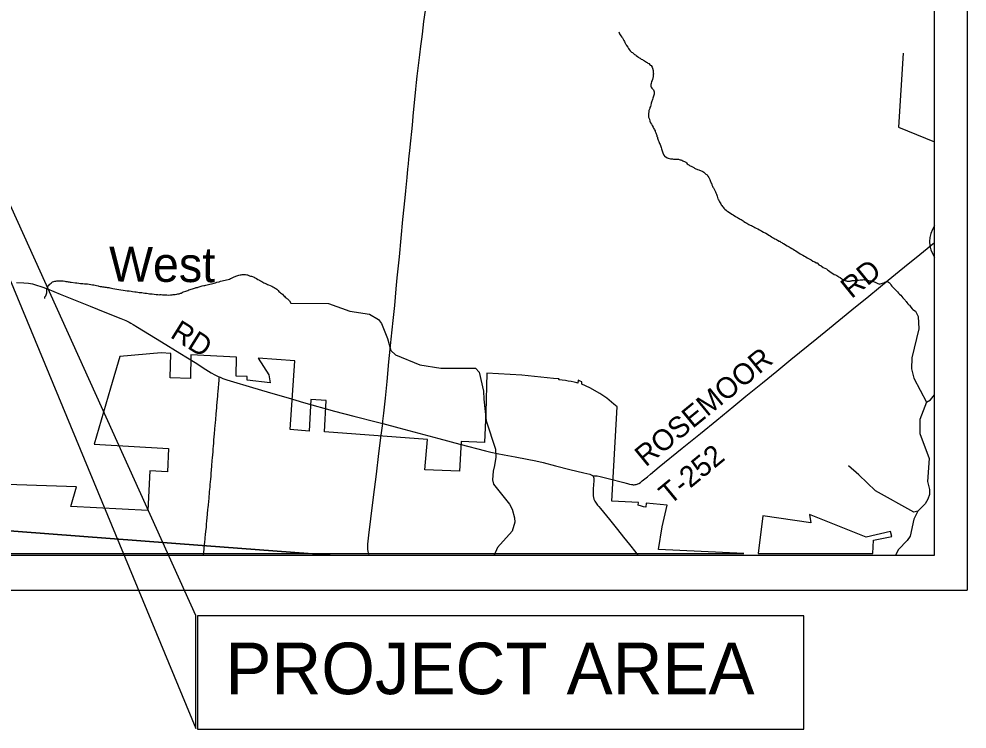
# Model space of a CAD drawing. Extents: x -5.4 to 49.9, y 13.2 to 48.4.
# Drawn here: x 30.593 to 33.165, y 40.172 to 42.099 of the extents above; entities that cross this region are included whole.
import ezdxf

# ---------------------------------------------------------------- set-up
doc = ezdxf.new("R2010")
doc.units = 0
for name, color, linetype in [('GM_X_Corporation', 7, 'Continuous'), ('GM_X_County_Road', 7, 'Continuous'), ('GM_X_County_Road_Text', 7, 'Continuous'), ('GM_X_Minor_River', 7, 'Continuous'), ('GM_X_Minor_River_Text', 7, 'Continuous'), ('GM_X_Township', 7, 'Continuous'), ('GM_X_Township_Road', 7, 'Continuous'), ('GM_X_Township_Road_Text', 7, 'Continuous'), ('GM_X_Unincorporated', 7, 'Continuous'), ('SH_Data', 7, 'Continuous'), ('SH_Text', 7, 'Continuous')]:
    doc.layers.add(name, color=color, linetype=linetype)

msp = doc.modelspace()

# ---------------------------------------------------------------- linework, layer by layer
at = {"layer": 'GM_X_Corporation'}
for p, q in [((30.2983, 40.6483), (32.5599, 40.6483)), ((32.5989, 40.6483), (32.9095, 40.6483))]:
    msp.add_line(p, q, dxfattribs=at)
for points in [[(32.5599, 40.6483), (32.3284, 40.6593), (32.3384, 40.7205), (32.352, 40.7792), (32.2946, 40.7848), (32.2935, 40.774), (32.2876, 40.7746), (32.2819, 40.7767), (32.2731, 40.7795), (32.2737, 40.7863), (32.2012, 40.7907), (32.2161, 41.0465), (32.2066, 41.0538), (32.1877, 41.0698), (32.1687, 41.083), (32.1417, 41.0976), (32.1201, 41.1078), (32.1204, 41.1139), (32.1158, 41.1162), (32.1099, 41.1187), (32.1095, 41.1109), (32.1062, 41.1117), (32.0993, 41.1134), (32.0911, 41.1151), (32.0832, 41.1165), (32.0755, 41.1177), (32.067, 41.1188), (32.058, 41.1197), (32.0582, 41.1226), (32.0437, 41.1235), (31.9571, 41.132), (31.8626, 41.1378), (31.8598, 41.0314), (31.8558, 40.9495), (31.793, 40.9527), (31.7884, 40.8713), (31.6943, 40.8754), (31.701, 40.9573), (31.4217, 40.9782), (31.4263, 41.0635), (31.3852, 41.0659), (31.3806, 40.9806), (31.3287, 40.9844), (31.341, 41.1714), (31.242, 41.1783), (31.271, 41.1337), (31.2748, 41.1119), (31.2125, 41.1187), (31.2125, 41.1286), (31.1825, 41.1299), (31.1833, 41.1814), (31.0595, 41.188), (31.058, 41.1229), (31.0031, 41.1251), (31.0054, 41.1909), (30.9785, 41.1928), (30.867, 41.183), (30.8414, 41.0973), (30.7971, 40.9452), (30.9983, 40.9337), (30.9961, 40.8703), (30.9477, 40.873), (30.9423, 40.765), (30.7337, 40.7761), (30.7487, 40.8288), (30.2884, 40.8443)], [(32.9095, 40.6483), (32.9114, 40.6846), (32.9609, 40.6942), (32.9579, 40.7081), (32.892, 40.6921), (32.7375, 40.7541), (32.7416, 40.7318), (32.611, 40.75), (32.5989, 40.6483)]]:
    msp.add_lwpolyline(points, dxfattribs=at)
at = {"layer": 'GM_X_County_Road'}
for points in [[(31.5798, 41.0007), (31.5805, 41.0071), (31.5826, 41.0288), (31.587, 41.0696), (31.5916, 41.1153), (31.5968, 41.1685), (31.6003, 41.2031), (31.603, 41.2297), (31.6082, 41.281), (31.6123, 41.3218), (31.6167, 41.3663), (31.6194, 41.3966), (31.6254, 41.454), (31.6349, 41.5549), (31.6407, 41.6136), (31.6425, 41.6328), (31.646, 41.6687), (31.6481, 41.6916), (31.6495, 41.7064), (31.6508, 41.7188), (31.6541, 41.7503), (31.6552, 41.7608), (31.6594, 41.8022), (31.6615, 41.822), (31.6628, 41.8356), (31.6701, 41.9086), (31.6719, 41.9265), (31.6737, 41.9438), (31.6763, 41.966), (31.6794, 41.9951), (31.6803, 42.0019), (31.6834, 42.0259), (31.6858, 42.0444), (31.6875, 42.0579), (31.6918, 42.0924), (31.6955, 42.1226)], [(30.5864, 41.3841), (30.6063, 41.383), (30.6187, 41.3819), (30.6298, 41.38), (30.6407, 41.3771), (30.6525, 41.373), (30.6699, 41.3663), (30.7051, 41.3522), (30.7863, 41.3194), (30.8255, 41.3035), (30.8694, 41.2861), (30.8826, 41.2805), (30.8916, 41.2763), (30.8966, 41.2737), (30.9032, 41.2701), (30.9149, 41.2629), (30.9307, 41.2531), (30.9799, 41.2228), (31.0295, 41.192), (31.0706, 41.1663), (31.0995, 41.148), (31.1148, 41.1386), (31.124, 41.1334), (31.1313, 41.1297), (31.1364, 41.1274)], [(31.1364, 41.1274), (31.1385, 41.1265), (31.1459, 41.1235), (31.157, 41.1197), (31.1749, 41.1142), (31.2172, 41.102), (31.2756, 41.0845), (31.3232, 41.0704), (31.365, 41.0582), (31.4488, 41.035), (31.5017, 41.0211), (31.5654, 41.0044), (31.5798, 41.0007)], [(31.5401, 40.6551), (31.5397, 40.6569), (31.5392, 40.6604), (31.5391, 40.6665), (31.5395, 40.6733), (31.5424, 40.6979), (31.548, 40.7423), (31.5525, 40.7793), (31.5577, 40.8219), (31.5628, 40.8632), (31.5694, 40.9194), (31.5755, 40.9693), (31.5798, 41.0007)], [(31.5798, 41.0007), (31.6232, 40.9895), (31.7318, 40.9605), (31.7895, 40.9453), (31.8591, 40.9267), (31.873, 40.9233), (31.8906, 40.9196), (31.9095, 40.916), (31.9389, 40.9108), (31.9719, 40.9045), (31.995, 40.8996), (32.015, 40.895), (32.0487, 40.8864), (32.0879, 40.8765), (32.1253, 40.8672), (32.1416, 40.8632), (32.1452, 40.862), (32.147, 40.8612), (32.1487, 40.8601), (32.1501, 40.8587)], [(32.1501, 40.8587), (32.1501, 40.8586), (32.1509, 40.8575), (32.152, 40.855), (32.1524, 40.8524), (32.1525, 40.8499), (32.1524, 40.8454), (32.1512, 40.8237), (32.1507, 40.8138), (32.1507, 40.8095), (32.151, 40.8046), (32.1516, 40.8001), (32.1531, 40.7956), (32.1557, 40.7903), (32.1594, 40.7847), (32.163, 40.7797), (32.1662, 40.7758), (32.1704, 40.7705), (32.1952, 40.7402), (32.2166, 40.7135), (32.2335, 40.6929), (32.2493, 40.6729), (32.2667, 40.6509), (32.2725, 40.6437)], [(31.5435, 40.6437), (31.5422, 40.6471), (31.5411, 40.6504), (31.5403, 40.6538), (31.5401, 40.6551)]]:
    msp.add_lwpolyline(points, dxfattribs=at)
at = {"layer": 'GM_X_Minor_River'}
for points in [[(32.2207, 42.0642), (32.2221, 42.0589), (32.2259, 42.0539), (32.2289, 42.0504), (32.2307, 42.0485), (32.2311, 42.0466), (32.2322, 42.0443), (32.2341, 42.0409), (32.2356, 42.0382), (32.2367, 42.0355), (32.2378, 42.0336), (32.2389, 42.0317), (32.24, 42.0298), (32.2411, 42.0275), (32.2445, 42.0225), (32.2464, 42.0195), (32.2486, 42.0168), (32.2516, 42.013), (32.2535, 42.0114), (32.255, 42.0095), (32.2573, 42.0083), (32.2595, 42.0064), (32.2614, 42.0052), (32.2633, 42.0033), (32.2655, 42.0022), (32.2678, 42.0002), (32.2716, 41.9972), (32.2738, 41.9956), (32.2757, 41.9941), (32.278, 41.9929), (32.2814, 41.9906), (32.2844, 41.989), (32.2863, 41.9879), (32.2885, 41.9867), (32.2904, 41.9855), (32.2927, 41.984), (32.2953, 41.9824), (32.2972, 41.9813), (32.2995, 41.9797), (32.3017, 41.9786), (32.3055, 41.9744), (32.3081, 41.9728), (32.3107, 41.9682), (32.3122, 41.9663), (32.3133, 41.9591), (32.314, 41.9534), (32.3143, 41.9507), (32.3135, 41.9473), (32.3135, 41.9442), (32.3135, 41.9416), (32.3127, 41.9393), (32.3119, 41.9351), (32.3107, 41.9321), (32.3095, 41.9295), (32.308, 41.9242), (32.3072, 41.9211), (32.3072, 41.9189), (32.3075, 41.917), (32.3086, 41.9143), (32.3105, 41.9116), (32.3127, 41.9089), (32.3146, 41.907), (32.3157, 41.9043), (32.3161, 41.902), (32.3164, 41.8994), (32.3164, 41.8975), (32.316, 41.8952), (32.3132, 41.8842), (32.3121, 41.8812), (32.3109, 41.8785), (32.3101, 41.8759), (32.3093, 41.8732), (32.3085, 41.8706), (32.3074, 41.8657), (32.3062, 41.8619), (32.305, 41.8592), (32.3042, 41.8566), (32.3038, 41.8543), (32.303, 41.8524), (32.3023, 41.8505), (32.3019, 41.8482), (32.3015, 41.8456), (32.3011, 41.8437), (32.301, 41.8414), (32.301, 41.8391), (32.301, 41.8365), (32.3013, 41.8327), (32.3024, 41.8289), (32.3035, 41.827), (32.3046, 41.8224), (32.3068, 41.8178), (32.3087, 41.8136), (32.3109, 41.8098), (32.3135, 41.8056), (32.315, 41.8029), (32.3165, 41.8006), (32.3176, 41.7983), (32.3188, 41.7956), (32.3195, 41.7937), (32.321, 41.7899), (32.3232, 41.7834)], [(32.9918, 42.0065), (32.9795, 41.8053), (33.0771, 41.7658)], [(32.3232, 41.7834), (32.3239, 41.7804), (32.325, 41.7781), (32.3258, 41.7758), (32.3265, 41.7735), (32.3276, 41.7704), (32.3291, 41.7666), (32.3302, 41.764), (32.3313, 41.7609), (32.3324, 41.7582), (32.3335, 41.7556), (32.3342, 41.7533), (32.335, 41.7506), (32.3361, 41.7472), (32.3372, 41.7445), (32.3379, 41.7415), (32.339, 41.7384), (32.3401, 41.7361), (32.3427, 41.7296), (32.3457, 41.7262), (32.3476, 41.725), (32.3518, 41.7223), (32.3548, 41.7211), (32.3604, 41.7195), (32.3639, 41.7195), (32.3658, 41.7195), (32.3684, 41.7191), (32.3768, 41.719), (32.3802, 41.7186), (32.3821, 41.7185), (32.384, 41.7181), (32.3866, 41.7173), (32.3889, 41.7169), (32.3911, 41.7158), (32.3938, 41.7146), (32.3961, 41.7138), (32.3991, 41.7123), (32.4021, 41.7107), (32.404, 41.7084), (32.4062, 41.7061), (32.4089, 41.7042), (32.4107, 41.703), (32.4126, 41.7015), (32.4145, 41.7003), (32.4164, 41.6995), (32.4187, 41.6987), (32.4221, 41.6968), (32.4239, 41.696), (32.4258, 41.6945), (32.4296, 41.6929), (32.4322, 41.6918), (32.4341, 41.691), (32.4372, 41.6894), (32.439, 41.689), (32.4421, 41.6878), (32.444, 41.6867), (32.4462, 41.6859), (32.4481, 41.6851), (32.4511, 41.6839), (32.4534, 41.6813), (32.4564, 41.6782), (32.4598, 41.6766), (32.462, 41.6728), (32.4643, 41.6686), (32.4665, 41.6655), (32.4676, 41.6632), (32.4683, 41.661), (32.4691, 41.6583), (32.4702, 41.656), (32.4713, 41.6537), (32.4724, 41.6514), (32.4732, 41.6491), (32.4746, 41.6457), (32.4757, 41.643), (32.4772, 41.6411), (32.4791, 41.6373), (32.481, 41.6335), (32.4824, 41.6304), (32.4839, 41.6277), (32.485, 41.6254), (32.4858, 41.6235), (32.4865, 41.6209), (32.4869, 41.6182), (32.4883, 41.6144), (32.4895, 41.6113), (32.4906, 41.6094), (32.4921, 41.6064), (32.4935, 41.6025), (32.4954, 41.5999), (32.4969, 41.5972), (32.4984, 41.5945), (32.5003, 41.5926), (32.5018, 41.5907), (32.5032, 41.5884), (32.5055, 41.5857), (32.5081, 41.5834), (32.5115, 41.5803), (32.5138, 41.5784), (32.516, 41.5768), (32.5232, 41.5722), (32.527, 41.5695)], [(32.527, 41.5695), (32.5311, 41.5672), (32.5341, 41.5652), (32.536, 41.5644), (32.5386, 41.5625), (32.5405, 41.5614), (32.5428, 41.5602), (32.5451, 41.559), (32.5473, 41.5575), (32.55, 41.5559), (32.5526, 41.5548), (32.5549, 41.5532), (32.5575, 41.5517), (32.5601, 41.5497), (32.5639, 41.547), (32.5677, 41.5447), (32.5733, 41.5416), (32.5767, 41.54), (32.5801, 41.5385), (32.5831, 41.5369), (32.5865, 41.5354), (32.5899, 41.5334), (32.5933, 41.5315), (32.5975, 41.5292), (32.602, 41.5268), (32.6058, 41.5249), (32.6088, 41.523), (32.6129, 41.5203), (32.619, 41.5175), (32.6235, 41.5148), (32.6277, 41.5125), (32.6311, 41.5106), (32.6344, 41.5082), (32.6375, 41.5063), (32.6409, 41.5044), (32.6439, 41.5028), (32.6461, 41.5013), (32.6484, 41.5005), (32.6514, 41.4989), (32.6552, 41.4966), (32.6571, 41.4958), (32.6601, 41.4935), (32.6624, 41.4923), (32.665, 41.4908), (32.6673, 41.4896), (32.6774, 41.4831), (32.6823, 41.4807), (32.6857, 41.4788), (32.6899, 41.4765), (32.6933, 41.4741), (32.697, 41.4718), (32.7008, 41.4695), (32.7046, 41.4668), (32.7087, 41.4641), (32.7129, 41.4621), (32.7163, 41.4598), (32.7197, 41.4579), (32.7242, 41.4555), (32.7276, 41.4536), (32.7317, 41.4509), (32.7366, 41.4478), (32.7423, 41.4451), (32.7472, 41.442), (32.7521, 41.4397), (32.7563, 41.4377), (32.7589, 41.4369), (32.7634, 41.4323), (32.7694, 41.4288), (32.7751, 41.425), (32.7796, 41.4226), (32.7838, 41.4207), (32.7864, 41.4187), (32.7898, 41.4164), (32.7928, 41.4137), (32.797, 41.411), (32.8015, 41.4083), (32.8052, 41.406), (32.8086, 41.4044), (32.8117, 41.4029), (32.8143, 41.401), (32.8169, 41.3994), (32.8196, 41.3982), (32.8215, 41.3971), (32.826, 41.3936), (32.8286, 41.3924), (32.8309, 41.3909), (32.8362, 41.3889), (32.8381, 41.3882), (32.84, 41.3877), (32.8426, 41.3877), (32.8449, 41.3877), (32.8479, 41.388), (32.8498, 41.3884), (32.8521, 41.3888), (32.854, 41.3891), (32.8563, 41.3895), (32.8582, 41.3894), (32.8605, 41.3898), (32.8631, 41.3901), (32.8673, 41.3905), (32.8707, 41.3904)], [(31.0209, 41.3524), (31.0239, 41.3528), (31.0274, 41.3535), (31.0308, 41.3546), (31.0331, 41.3549), (31.0354, 41.3564), (31.0384, 41.3583), (31.0418, 41.3594), (31.0456, 41.3605), (31.0483, 41.3616), (31.051, 41.3623), (31.054, 41.3638), (31.0578, 41.3645), (31.0605, 41.3657), (31.0635, 41.3668), (31.0662, 41.3675), (31.0689, 41.3686), (31.0715, 41.3693), (31.0738, 41.3701), (31.0772, 41.3708), (31.0795, 41.3715), (31.0818, 41.3723), (31.0849, 41.3734), (31.0902, 41.3748), (31.0944, 41.3755), (31.097, 41.3759), (31.0997, 41.377), (31.1035, 41.3777), (31.1069, 41.3784), (31.1107, 41.3795), (31.1149, 41.3806), (31.1259, 41.3832), (31.1301, 41.3846), (31.1358, 41.3857), (31.14, 41.3872), (31.1442, 41.3883), (31.148, 41.3894), (31.1522, 41.3905), (31.1564, 41.3916), (31.1606, 41.3923), (31.164, 41.3934), (31.167, 41.3945), (31.1697, 41.3956), (31.1728, 41.3974), (31.177, 41.3989), (31.1796, 41.4), (31.1815, 41.4008), (31.1838, 41.4019), (31.1869, 41.403), (31.1899, 41.4037), (31.1933, 41.4048), (31.196, 41.4052), (31.1987, 41.4055), (31.2009, 41.4059), (31.2032, 41.4058), (31.2051, 41.4058), (31.2078, 41.4054), (31.2108, 41.405), (31.2127, 41.4046), (31.2165, 41.403), (31.2187, 41.4022), (31.221, 41.4015), (31.224, 41.4007), (31.227, 41.3999), (31.2312, 41.3987), (31.2342, 41.3968), (31.2376, 41.3948), (31.2414, 41.3925), (31.2452, 41.3902), (31.2486, 41.3882), (31.2519, 41.3863), (31.255, 41.3847), (31.2572, 41.3832), (31.2599, 41.3824), (31.2621, 41.3812), (31.2644, 41.3801), (31.2674, 41.3789), (31.2704, 41.3777), (31.2788, 41.3738), (31.2818, 41.3719), (31.2852, 41.37), (31.2878, 41.3684), (31.2901, 41.3672), (31.2923, 41.3657), (31.2965, 41.3619), (31.2983, 41.3599), (31.3006, 41.3576), (31.3028, 41.3557), (31.3051, 41.3545), (31.3077, 41.3522), (31.3107, 41.3488), (31.313, 41.3465), (31.3152, 41.3442), (31.3179, 41.3422), (31.3198, 41.3407), (31.3216, 41.3395), (31.3239, 41.3372), (31.3265, 41.3345), (31.3303, 41.3282)], [(32.8707, 41.3904), (32.8753, 41.3911), (32.8795, 41.3911), (32.8825, 41.3914), (32.8848, 41.3918), (32.8874, 41.3914), (32.8893, 41.3914), (32.892, 41.391), (32.8946, 41.3906), (32.8992, 41.3897), (32.9022, 41.3889), (32.9045, 41.3889), (32.9064, 41.3881), (32.9098, 41.3873), (32.9117, 41.3866), (32.9135, 41.3858), (32.9162, 41.3846), (32.92, 41.383), (32.923, 41.3815), (32.9256, 41.3799), (32.9279, 41.3792), (32.9298, 41.3803), (32.9397, 41.3832), (32.9424, 41.3847), (32.9447, 41.3858), (32.9473, 41.3865), (32.9496, 41.3865), (32.9519, 41.385), (32.9549, 41.3834), (32.9564, 41.3815), (32.9582, 41.3777), (32.9612, 41.3742), (32.9639, 41.3712), (32.9669, 41.3681), (32.9687, 41.3665), (32.9706, 41.365), (32.974, 41.3612), (32.977, 41.3585), (32.9792, 41.3554), (32.9819, 41.3523), (32.9853, 41.3493), (32.9886, 41.3458), (32.9909, 41.3427), (32.9935, 41.3397), (32.9958, 41.3377), (32.9973, 41.3358), (32.9987, 41.3339), (33.0002, 41.332), (33.0021, 41.3293), (33.0044, 41.3262), (33.007, 41.3236), (33.0089, 41.322), (33.0126, 41.3174), (33.016, 41.3128), (33.0186, 41.3109), (33.0255, 41.3059)], [(30.6633, 41.3405), (30.6634, 41.3447), (30.6661, 41.3481), (30.6681, 41.3556), (30.6685, 41.3575), (30.6685, 41.3602), (30.6685, 41.3625), (30.6689, 41.3651), (30.6693, 41.3674), (30.6701, 41.3697), (30.6713, 41.3719), (30.6713, 41.3746), (30.674, 41.3761), (30.6755, 41.3784), (30.6778, 41.3802), (30.6805, 41.3825), (30.6824, 41.3836), (30.6839, 41.3855), (30.6874, 41.3866), (30.69, 41.3873), (30.6927, 41.3877), (30.6961, 41.3884), (30.6991, 41.3887), (30.7026, 41.3887), (30.7067, 41.3886), (30.7101, 41.3886), (30.7132, 41.3882), (30.7173, 41.3878), (30.7204, 41.387), (30.7234, 41.3866), (30.7264, 41.3861), (30.7291, 41.3854), (30.7317, 41.3849), (30.7348, 41.3845), (30.7461, 41.3833), (30.7503, 41.3828), (30.7556, 41.3824), (30.7598, 41.3816), (30.7658, 41.3811), (30.7708, 41.3807), (30.7746, 41.3803), (30.7787, 41.3799), (30.7837, 41.379), (30.7882, 41.3786), (30.7924, 41.3778), (30.7962, 41.3774), (30.7999, 41.3766), (30.8037, 41.3754), (30.8075, 41.375), (30.8098, 41.3742), (30.8136, 41.3734), (30.817, 41.373), (30.82, 41.3725), (30.823, 41.3718), (30.8257, 41.3717), (30.8291, 41.3713), (30.8325, 41.3705), (30.8367, 41.3701), (30.8397, 41.3697), (30.8439, 41.3689), (30.8473, 41.3677), (30.8526, 41.3669), (30.8583, 41.366), (30.8643, 41.3648), (30.8696, 41.364), (30.8757, 41.3632), (30.8814, 41.3624), (30.8867, 41.3615), (30.892, 41.3611), (30.8969, 41.3603), (30.9007, 41.3595), (30.9071, 41.3586), (30.9113, 41.3582), (30.9155, 41.3578), (30.9193, 41.357), (30.9227, 41.3566), (30.9261, 41.3565), (30.9295, 41.3557), (30.934, 41.3553), (30.939, 41.3549), (30.9435, 41.3541), (30.9473, 41.3536), (30.9515, 41.3528), (30.9541, 41.3528), (30.9651, 41.3512), (30.9693, 41.3511), (30.9731, 41.3507), (30.9761, 41.351), (30.9788, 41.351), (30.9825, 41.3506), (30.9856, 41.3502), (30.9879, 41.3501), (30.9909, 41.3501), (30.9943, 41.3501), (30.9989, 41.35), (31.0038, 41.3503), (31.0084, 41.3507), (31.0114, 41.351), (31.0141, 41.3514), (31.0163, 41.3517), (31.0209, 41.3524)], [(31.3303, 41.3282), (31.4329, 41.3269)], [(31.4329, 41.3269), (31.4909, 41.3063), (31.5437, 41.2984), (31.5683, 41.2833), (31.577, 41.273), (31.5929, 41.2321), (31.6021, 41.1989), (31.6145, 41.1877), (31.6805, 41.1607), (31.7375, 41.1513), (31.832, 41.1518), (31.8418, 41.1402), (31.8534, 41.0892), (31.8543, 41.0675), (31.8609, 41.0081), (31.8857, 40.9317), (31.8866, 40.9093), (31.8829, 40.8869), (31.8793, 40.8721), (31.8779, 40.8482), (31.8809, 40.8367), (31.9241, 40.7818), (31.9315, 40.7684), (31.9378, 40.7452), (31.938, 40.733), (31.9313, 40.7087), (31.8912, 40.6643), (31.8822, 40.6437)], [(33.0255, 41.3059), (33.0325, 41.292), (33.0344, 41.2585), (33.0157, 41.1793), (33.0146, 41.1492), (33.0209, 41.1244), (33.0556, 41.0594), (33.0368, 41.0117), (33.0368, 40.974), (33.0624, 40.9061), (33.0583, 40.8441), (33.0634, 40.822), (33.0632, 40.8083), (33.0593, 40.7954), (33.0516, 40.783), (33.0315, 40.7627), (33.021, 40.7415), (33.0107, 40.6956), (33.0029, 40.6831), (32.9794, 40.6591), (32.9709, 40.6437)], [(33.0556, 41.0594), (33.0663, 41.0654), (33.0771, 41.0793)], [(33.0315, 40.7627), (33.0212, 40.7601), (32.9168, 40.818), (32.8715, 40.8619), (32.844, 40.8861)]]:
    msp.add_lwpolyline(points, dxfattribs=at)
at = {"layer": 'GM_X_Township'}
msp.add_line((28.3741, 40.6437), (31.4373, 40.6437), dxfattribs=at)
for points in [[(31.4373, 40.6437), (33.0771, 40.6437), (33.0771, 44.431)], [(31.4373, 40.6437), (31.09, 40.6701), (29.9244, 40.7587), (29.4619, 40.7938), (28.3929, 40.8821), (28.3919, 40.8674), (28.3741, 40.6437)], [(28.3741, 40.6437), (28.3919, 40.8674), (28.3929, 40.8821), (29.4619, 40.7938), (29.9244, 40.7587), (31.09, 40.6701), (31.4373, 40.6437)]]:
    msp.add_lwpolyline(points, dxfattribs=at)
at = {"layer": 'GM_X_Township_Road'}
for points in [[(32.1501, 40.8587), (32.1527, 40.8591), (32.1546, 40.8594), (32.1566, 40.8594), (32.1591, 40.8593), (32.1613, 40.8591), (32.1697, 40.8572), (32.192, 40.8515), (32.2342, 40.8406), (32.2408, 40.839), (32.2444, 40.8379), (32.2499, 40.8367), (32.2547, 40.8356), (32.2572, 40.8352), (32.2595, 40.835), (32.2623, 40.8349), (32.2651, 40.8351), (32.2675, 40.8355), (32.2699, 40.8363), (32.2723, 40.8372), (32.2751, 40.8386), (32.2793, 40.8413), (32.2842, 40.8451), (32.298, 40.8567), (32.3066, 40.8639), (32.33, 40.8835), (32.3927, 40.9343), (32.4419, 40.9743), (32.4861, 41.0105), (32.5328, 41.0486), (32.5651, 41.0749), (32.6099, 41.1114), (32.6494, 41.1436), (32.6874, 41.1748), (32.7573, 41.2316), (32.7918, 41.2601), (32.8531, 41.3098), (32.8988, 41.3472), (32.9512, 41.3901), (32.9715, 41.4065), (33.0058, 41.4343), (33.0274, 41.452), (33.0771, 41.4923)], [(31.0985, 40.6906), (31.0994, 40.6997), (31.1002, 40.7077), (31.1014, 40.7201), (31.102, 40.7275), (31.1028, 40.7367), (31.1036, 40.7454), (31.1045, 40.7547), (31.1058, 40.7689), (31.1061, 40.772), (31.1069, 40.7806), (31.1071, 40.7825), (31.1077, 40.7879), (31.1088, 40.8002), (31.109, 40.8039), (31.1096, 40.8095), (31.1101, 40.8156), (31.1108, 40.8224), (31.1113, 40.8286), (31.112, 40.8354), (31.1126, 40.8428), (31.1134, 40.8502), (31.114, 40.8582), (31.1147, 40.8663), (31.1153, 40.8743), (31.1163, 40.8861), (31.1174, 40.9003), (31.118, 40.9078), (31.1187, 40.9164), (31.1194, 40.9245), (31.12, 40.9319), (31.1206, 40.9399), (31.1212, 40.948), (31.1218, 40.956), (31.1227, 40.9659), (31.1232, 40.9721), (31.1245, 40.987), (31.1252, 40.9956), (31.1258, 41.0031), (31.1267, 41.0117), (31.128, 41.0266), (31.1289, 41.0365), (31.1294, 41.0426), (31.13, 41.0494), (31.1308, 41.0587), (31.1315, 41.0674), (31.1322, 41.0754), (31.1326, 41.081), (31.1332, 41.0884), (31.1357, 41.1188), (31.1364, 41.1274)], [(31.0938, 40.6437), (31.0955, 40.6595), (31.0967, 40.6731), (31.0972, 40.678), (31.0983, 40.6885), (31.0985, 40.6906)]]:
    msp.add_lwpolyline(points, dxfattribs=at)
at = {"layer": 'GM_X_Unincorporated'}
msp.add_line((33.0771, 41.4525), (33.0771, 41.5375), dxfattribs=at)
msp.add_arc((33.1382, 41.495), 0.0744, 145.1591, 214.8409, dxfattribs=at)
at = {"layer": 'SH_Data'}
for p in [(33.1653, 47.5483), (26.1653, 40.5483)]:
    msp.add_line(p, (33.1653, 40.5483), dxfattribs=at)
for points in [[(31.0729, 40.4803), (29.5617, 43.8236), (31.0729, 40.1733)], [(31.0776, 40.1716), (32.7228, 40.1716), (32.7228, 40.4786), (31.0776, 40.4786)]]:
    msp.add_lwpolyline(points, close=True, dxfattribs=at)

# ---------------------------------------------------------------- texts
at = {"layer": 'GM_X_County_Road_Text'}
msp.add_text('RD', height=0.05682, rotation=327.9423, dxfattribs=at).set_placement((31.0004, 41.2365))
at = {"layer": 'GM_X_Minor_River_Text'}
msp.add_text('West', height=0.0947, rotation=359.5484, dxfattribs=at).set_placement((30.8366, 41.3869))
at = {"layer": 'GM_X_Township_Road_Text'}
for s, rotation, p in [('RD', 39.0466, (32.8518, 41.3383)), ('ROSEMOOR', 39.3153, (32.2934, 40.8816)), ('T-252', 39.4851, (32.3588, 40.7783))]:
    msp.add_text(s, height=0.05682, rotation=rotation, dxfattribs=at).set_placement(p)
at = {"layer": 'SH_Text'}
msp.add_text('PROJECT AREA', height=0.14, dxfattribs=at).set_placement((31.1531, 40.2662))

doc.saveas('drawing.dxf')
